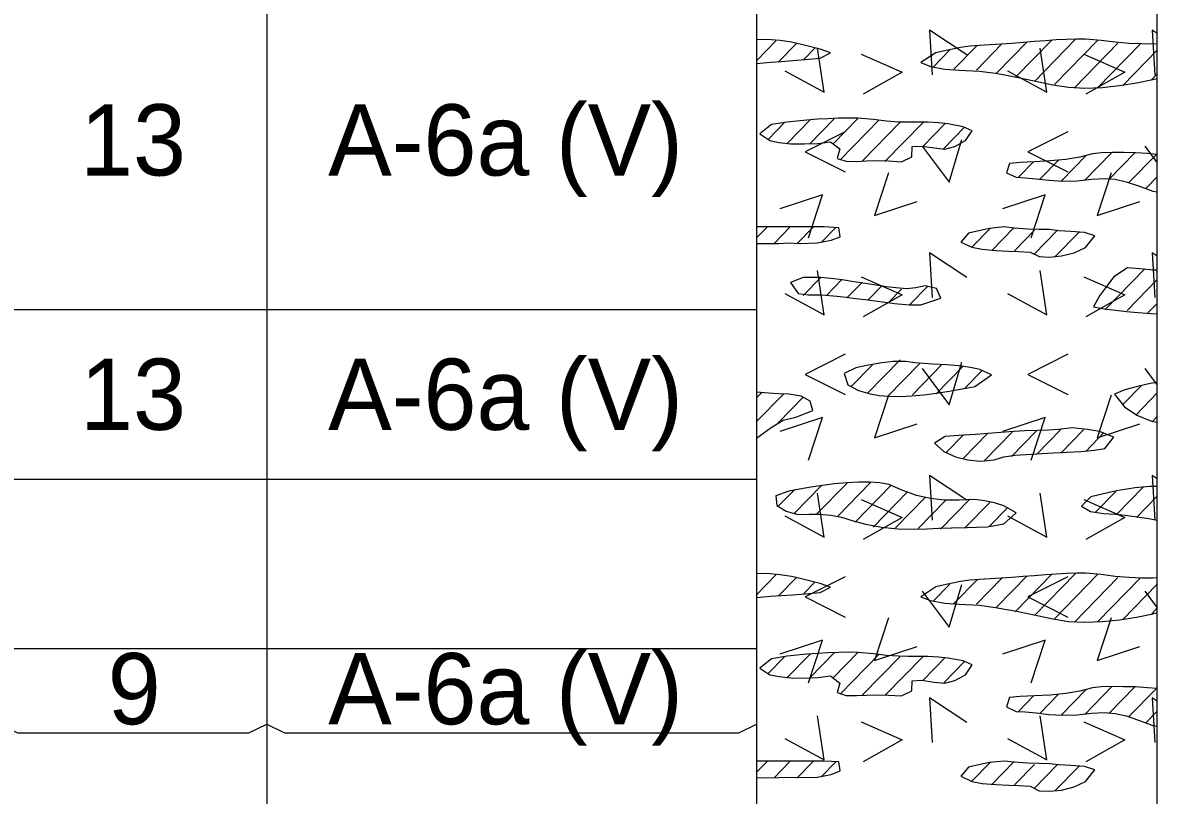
# Model space of a CAD drawing. Extents: x 0 to 0.833, y -0.323 to 0.608.
# Drawn here: x 0.7272 to 0.8333, y 0.2085 to 0.2808 of the extents above; entities that cross this region are included whole.
import ezdxf

# ---------------------------------------------------------------- set-up
doc = ezdxf.new("R2010")
doc.units = 0

msp = doc.modelspace()

# ---------------------------------------------------------------- linework, layer by layer
for points in [[(0, -0.32328), (0.83333, -0.32328), (0.83333, 0.60833), (0, 0.60833)], [(0.79583, 0.27704), (0.79715, 0.27715), (0.79814, 0.27722), (0.79922, 0.2773), (0.80039, 0.27739), (0.80179, 0.27751), (0.80275, 0.27802), (0.80179, 0.27836), (0.80091, 0.27858), (0.80003, 0.2788), (0.79909, 0.27901), (0.79803, 0.27917), (0.79677, 0.27927), (0.79583, 0.27925)], [(0.82816, 0.27479), (0.82978, 0.27496), (0.83137, 0.27521), (0.8329, 0.27552), (0.83333, 0.27563), (0.83333, 0.27887), (0.83295, 0.27884), (0.83188, 0.27886), (0.83071, 0.27891), (0.82938, 0.27901), (0.82807, 0.27918), (0.82662, 0.2793), (0.82576, 0.2793), (0.82484, 0.27928), (0.82387, 0.27923), (0.82286, 0.27916), (0.82182, 0.27908), (0.82077, 0.27899), (0.81973, 0.27891), (0.81872, 0.27884), (0.81715, 0.27874), (0.81579, 0.27865), (0.81491, 0.27852), (0.81357, 0.27824), (0.8126, 0.27803), (0.81121, 0.27711), (0.8121, 0.27675), (0.81345, 0.2765), (0.81479, 0.27641), (0.81668, 0.27631), (0.81818, 0.27611), (0.81905, 0.27596), (0.82, 0.27578), (0.82107, 0.27557), (0.82225, 0.27532), (0.82357, 0.27503), (0.82501, 0.2748), (0.82656, 0.27473)], [(0.79708, 0.26981), (0.79794, 0.26963), (0.79904, 0.26952), (0.80028, 0.26949), (0.80156, 0.26954), (0.80274, 0.2697), (0.80361, 0.26903), (0.80338, 0.26814), (0.80422, 0.26787), (0.80517, 0.26785), (0.80613, 0.2679), (0.8072, 0.26793), (0.80818, 0.2679), (0.80939, 0.26783), (0.81037, 0.2683), (0.81038, 0.26924), (0.8113, 0.2693), (0.81244, 0.26912), (0.81346, 0.26901), (0.81438, 0.26927), (0.81539, 0.26981), (0.81601, 0.27072), (0.81517, 0.2711), (0.81374, 0.27137), (0.81285, 0.27146), (0.81187, 0.27152), (0.81, 0.27152), (0.8091, 0.27154), (0.808, 0.27162), (0.80678, 0.27177), (0.8053, 0.2719), (0.80443, 0.27192), (0.80349, 0.2719), (0.80251, 0.27186), (0.80152, 0.2718), (0.80054, 0.27172), (0.79959, 0.27163), (0.7987, 0.27153), (0.79722, 0.27131), (0.79614, 0.27043)], [(0.83241, 0.26859), (0.83129, 0.26866), (0.83017, 0.26869), (0.8291, 0.2687), (0.82811, 0.26866), (0.82728, 0.26857), (0.82608, 0.26827), (0.82476, 0.26804), (0.8233, 0.26791), (0.82183, 0.26782), (0.82051, 0.26776), (0.81951, 0.26767), (0.81922, 0.2668), (0.82013, 0.26638), (0.82097, 0.26633), (0.822, 0.26623), (0.82318, 0.2661), (0.82448, 0.26601), (0.82584, 0.26604), (0.82719, 0.2662), (0.82836, 0.26627), (0.8294, 0.26619), (0.83043, 0.26595), (0.83156, 0.26556), (0.83291, 0.26507), (0.83333, 0.265), (0.83333, 0.26852)], [(0.79583, 0.26018), (0.79676, 0.26017), (0.79792, 0.26019), (0.79882, 0.26023), (0.79992, 0.26018), (0.80151, 0.26023), (0.80282, 0.26048), (0.80367, 0.2608), (0.80354, 0.26164), (0.80216, 0.26173), (0.79583, 0.26173)], [(0.81822, 0.25953), (0.81944, 0.25947), (0.82033, 0.25943), (0.82145, 0.25937), (0.82229, 0.25895), (0.82324, 0.25891), (0.82438, 0.25901), (0.82555, 0.2593), (0.82662, 0.25981), (0.82749, 0.2609), (0.82651, 0.26121), (0.82524, 0.26131), (0.82413, 0.26137), (0.82324, 0.26148), (0.82226, 0.2615), (0.82121, 0.26152), (0.81995, 0.26161), (0.81902, 0.26173), (0.81761, 0.26159), (0.81566, 0.26114), (0.81496, 0.26031), (0.81598, 0.25982), (0.81695, 0.25964)], [(0.80066, 0.25538), (0.80188, 0.25537), (0.80339, 0.25524), (0.80423, 0.25515), (0.8051, 0.25504), (0.806, 0.25492), (0.80692, 0.2548), (0.80784, 0.25468), (0.80875, 0.25457), (0.81014, 0.25443), (0.81119, 0.25444), (0.81222, 0.25478), (0.81308, 0.25507), (0.81267, 0.25597), (0.8116, 0.25622), (0.81075, 0.25602), (0.80989, 0.25594), (0.80885, 0.25602), (0.80799, 0.25613), (0.80703, 0.25627), (0.806, 0.25644), (0.80492, 0.2566), (0.80384, 0.25676), (0.8028, 0.25689), (0.80182, 0.25698), (0.8002, 0.25699), (0.79901, 0.25652), (0.79974, 0.25548)], [(0.83305, 0.25768), (0.83171, 0.25779), (0.83054, 0.25789), (0.82925, 0.25707), (0.82857, 0.25616), (0.82792, 0.25527), (0.82735, 0.25425), (0.82858, 0.25402), (0.82945, 0.25392), (0.83045, 0.25382), (0.83155, 0.25373), (0.83272, 0.25363), (0.83333, 0.25358), (0.83333, 0.25767)], [(0.81233, 0.24887), (0.81063, 0.24899), (0.80977, 0.24912), (0.8086, 0.24913), (0.80755, 0.24899), (0.80632, 0.24879), (0.80513, 0.24854), (0.80403, 0.24802), (0.80436, 0.24696), (0.80536, 0.2464), (0.80647, 0.2461), (0.8073, 0.24595), (0.80824, 0.24587), (0.80926, 0.24586), (0.81035, 0.24591), (0.81149, 0.24601), (0.81267, 0.24616), (0.81386, 0.24635), (0.81506, 0.24656), (0.81625, 0.24679), (0.81783, 0.24787), (0.81673, 0.24837), (0.81585, 0.24857), (0.8148, 0.24873), (0.81361, 0.24883)], [(0.83265, 0.24706), (0.83136, 0.24675), (0.83028, 0.24647), (0.82934, 0.24608), (0.83026, 0.24488), (0.83142, 0.24412), (0.83279, 0.24354), (0.83333, 0.24344), (0.83333, 0.24715)], [(0.79583, 0.24196), (0.79719, 0.24295), (0.79831, 0.24365), (0.79951, 0.24393), (0.80111, 0.24453), (0.80086, 0.24541), (0.80002, 0.24589), (0.79889, 0.24608), (0.79791, 0.24611), (0.79694, 0.24617), (0.79583, 0.24625)], [(0.82537, 0.24291), (0.82408, 0.24276), (0.82319, 0.2427), (0.82214, 0.24267), (0.82091, 0.24264), (0.81947, 0.24255), (0.81792, 0.24242), (0.81632, 0.2423), (0.81475, 0.24221), (0.81348, 0.24211), (0.81247, 0.24147), (0.81337, 0.24071), (0.81444, 0.24021), (0.81561, 0.23992), (0.81675, 0.23981), (0.81807, 0.23993), (0.81896, 0.2402), (0.82003, 0.24035), (0.82157, 0.24047), (0.82253, 0.24053), (0.82362, 0.24058), (0.82483, 0.24065), (0.82618, 0.24071), (0.82745, 0.24082), (0.82842, 0.24099), (0.82927, 0.24205), (0.82791, 0.24257), (0.82679, 0.24277)], [(0.79885, 0.237), (0.79763, 0.23654), (0.79773, 0.23564), (0.79859, 0.23512), (0.7997, 0.23482), (0.80074, 0.23483), (0.80165, 0.23484), (0.80281, 0.23476), (0.80377, 0.23455), (0.80486, 0.2342), (0.80606, 0.23391), (0.80751, 0.23363), (0.80905, 0.23345), (0.81052, 0.23342), (0.81177, 0.23347), (0.81289, 0.23352), (0.81408, 0.23355), (0.81553, 0.23359), (0.81642, 0.23362), (0.81745, 0.23365), (0.81897, 0.23392), (0.82011, 0.23496), (0.81896, 0.23563), (0.8181, 0.23589), (0.81717, 0.23609), (0.81626, 0.2362), (0.81479, 0.23614), (0.81343, 0.23614), (0.8121, 0.23629), (0.8108, 0.23659), (0.80953, 0.23705), (0.8082, 0.2376), (0.80736, 0.23776), (0.8064, 0.23784), (0.80536, 0.23784), (0.80427, 0.23778), (0.80314, 0.23767), (0.80201, 0.23752), (0.8009, 0.23735), (0.79984, 0.23717)], [(0.83263, 0.23744), (0.83126, 0.23731), (0.82969, 0.23704), (0.82883, 0.23687), (0.82712, 0.23646), (0.82623, 0.23559), (0.82708, 0.2351), (0.82831, 0.23491), (0.82941, 0.23484), (0.83033, 0.23475), (0.83165, 0.23457), (0.83253, 0.23443), (0.83333, 0.23429), (0.83333, 0.23744)], [(0.79583, 0.22704), (0.79715, 0.22715), (0.79814, 0.22722), (0.79922, 0.2273), (0.80039, 0.22739), (0.80179, 0.22751), (0.80275, 0.22802), (0.80179, 0.22836), (0.80091, 0.22858), (0.80003, 0.2288), (0.79909, 0.22901), (0.79803, 0.22917), (0.79677, 0.22927), (0.79583, 0.22925)], [(0.82816, 0.22479), (0.82978, 0.22496), (0.83137, 0.22521), (0.8329, 0.22552), (0.83333, 0.22563), (0.83333, 0.22887), (0.83295, 0.22884), (0.83188, 0.22886), (0.83071, 0.22891), (0.82938, 0.22901), (0.82807, 0.22918), (0.82662, 0.2293), (0.82576, 0.2293), (0.82484, 0.22928), (0.82387, 0.22923), (0.82286, 0.22916), (0.82182, 0.22908), (0.82077, 0.22899), (0.81973, 0.22891), (0.81872, 0.22884), (0.81715, 0.22874), (0.81579, 0.22865), (0.81491, 0.22852), (0.81357, 0.22824), (0.8126, 0.22803), (0.81121, 0.22711), (0.8121, 0.22675), (0.81345, 0.2265), (0.81479, 0.22641), (0.81668, 0.22631), (0.81818, 0.22611), (0.81905, 0.22596), (0.82, 0.22578), (0.82107, 0.22557), (0.82225, 0.22532), (0.82357, 0.22503), (0.82501, 0.2248), (0.82656, 0.22473)], [(0.79708, 0.21981), (0.79794, 0.21963), (0.79904, 0.21952), (0.80028, 0.21949), (0.80156, 0.21954), (0.80274, 0.2197), (0.80361, 0.21903), (0.80338, 0.21814), (0.80422, 0.21787), (0.80517, 0.21785), (0.80613, 0.2179), (0.8072, 0.21793), (0.80818, 0.2179), (0.80939, 0.21783), (0.81037, 0.2183), (0.81038, 0.21924), (0.8113, 0.2193), (0.81244, 0.21912), (0.81346, 0.21901), (0.81438, 0.21927), (0.81539, 0.21981), (0.81601, 0.22072), (0.81517, 0.2211), (0.81374, 0.22137), (0.81285, 0.22146), (0.81187, 0.22152), (0.81, 0.22152), (0.8091, 0.22154), (0.808, 0.22162), (0.80678, 0.22177), (0.8053, 0.2219), (0.80443, 0.22192), (0.80349, 0.2219), (0.80251, 0.22186), (0.80152, 0.2218), (0.80054, 0.22172), (0.79959, 0.22163), (0.7987, 0.22153), (0.79722, 0.22131), (0.79614, 0.22043)], [(0.83241, 0.21859), (0.83129, 0.21866), (0.83017, 0.21869), (0.8291, 0.2187), (0.82811, 0.21866), (0.82728, 0.21857), (0.82608, 0.21827), (0.82476, 0.21804), (0.8233, 0.21791), (0.82183, 0.21782), (0.82051, 0.21776), (0.81951, 0.21767), (0.81922, 0.2168), (0.82013, 0.21638), (0.82097, 0.21633), (0.822, 0.21623), (0.82318, 0.2161), (0.82448, 0.21601), (0.82584, 0.21604), (0.82719, 0.2162), (0.82836, 0.21627), (0.8294, 0.21619), (0.83043, 0.21595), (0.83156, 0.21556), (0.83291, 0.21507), (0.83333, 0.215), (0.83333, 0.21852)], [(0.79583, 0.21018), (0.79676, 0.21017), (0.79792, 0.21019), (0.79882, 0.21023), (0.79992, 0.21018), (0.80151, 0.21023), (0.80282, 0.21048), (0.80367, 0.2108), (0.80354, 0.21164), (0.80216, 0.21173), (0.79583, 0.21173)], [(0.81822, 0.20953), (0.81944, 0.20948), (0.82033, 0.20943), (0.82145, 0.20937), (0.82229, 0.20895), (0.82324, 0.20891), (0.82438, 0.20901), (0.82555, 0.2093), (0.82662, 0.20981), (0.82749, 0.2109), (0.82651, 0.21121), (0.82524, 0.21131), (0.82413, 0.21137), (0.82324, 0.21148), (0.82226, 0.2115), (0.82121, 0.21152), (0.81995, 0.21161), (0.81902, 0.21173), (0.81761, 0.21159), (0.81566, 0.21114), (0.81496, 0.21031), (0.81598, 0.20982), (0.81695, 0.20964)]]:
    msp.add_lwpolyline(points, close=True)
for points in [[(0.75, 0.55417), (0.75, -0.28575)], [(0.75, 0.55417), (0.75, -0.28575)], [(0.79583, 0.55417), (0.79583, -0.28575)], [(0.83333, -0.28575), (0.83333, 0.50165)], [(0.81551, 0.27783), (0.81201, 0.28014), (0.81226, 0.27595)], [(0.82569, 0.27929), (0.82184, 0.27535)], [(0.83333, 0.27982), (0.83284, 0.28014), (0.83309, 0.27595)], [(0.79765, 0.27915), (0.79583, 0.27728)], [(0.7996, 0.27894), (0.79786, 0.27715)], [(0.79847, 0.27634), (0.80215, 0.27434), (0.80153, 0.27847)], [(0.8013, 0.27846), (0.80027, 0.27741)], [(0.81392, 0.2783), (0.81235, 0.27669)], [(0.8143, 0.27648), (0.8165, 0.27873)], [(0.8164, 0.27641), (0.81879, 0.27886)], [(0.81829, 0.27613), (0.82114, 0.27905)], [(0.8193, 0.27634), (0.82299, 0.27434), (0.82236, 0.27847)], [(0.82004, 0.27571), (0.82346, 0.27922)], [(0.82775, 0.27919), (0.8237, 0.27505)], [(0.82964, 0.27892), (0.82557, 0.27474)], [(0.83173, 0.27885), (0.82774, 0.27476)], [(0.83333, 0.27827), (0.83012, 0.27498)], [(0.80562, 0.27789), (0.80946, 0.27621), (0.80581, 0.27414)], [(0.82645, 0.27789), (0.83029, 0.27621), (0.82664, 0.27414)], [(0.83281, 0.27552), (0.83333, 0.27606)], [(0.80083, 0.26951), (0.80311, 0.27185)], [(0.80534, 0.27192), (0.80299, 0.26951)], [(0.79844, 0.27149), (0.79691, 0.26992)], [(0.79871, 0.26955), (0.80085, 0.27174)], [(0.80367, 0.268), (0.80732, 0.27174)], [(0.80571, 0.26788), (0.80924, 0.27149)], [(0.81142, 0.27151), (0.80785, 0.26786)], [(0.81141, 0.26929), (0.81348, 0.27141)], [(0.81528, 0.27105), (0.81331, 0.26903)], [(0.80412, 0.27063), (0.80038, 0.26876), (0.80412, 0.26688)], [(0.81134, 0.26929), (0.81384, 0.26591), (0.81503, 0.26991)], [(0.82496, 0.27063), (0.82121, 0.26876), (0.82496, 0.26688)], [(0.82909, 0.2687), (0.82656, 0.2661)], [(0.82885, 0.26623), (0.83122, 0.26866)], [(0.83217, 0.26929), (0.83333, 0.26773)], [(0.82035, 0.26637), (0.82176, 0.26782)], [(0.82233, 0.26619), (0.82408, 0.26798)], [(0.82433, 0.26602), (0.82666, 0.26841)], [(0.83325, 0.26852), (0.83065, 0.26586)], [(0.80818, 0.2668), (0.80687, 0.2628), (0.81087, 0.26411)], [(0.82901, 0.2668), (0.8277, 0.2628), (0.8317, 0.26411)], [(0.83333, 0.2664), (0.83227, 0.26531)], [(0.80069, 0.26072), (0.802, 0.26472), (0.798, 0.26341)], [(0.82152, 0.26072), (0.82284, 0.26472), (0.81884, 0.26341)], [(0.79583, 0.2607), (0.79681, 0.2617)], [(0.79898, 0.26172), (0.79747, 0.26017)], [(0.80116, 0.26173), (0.79959, 0.26013)], [(0.80328, 0.26169), (0.80188, 0.26026)], [(0.8177, 0.26159), (0.81596, 0.25981)], [(0.81988, 0.26161), (0.81785, 0.25953)], [(0.82185, 0.26142), (0.81997, 0.25949)], [(0.824, 0.26141), (0.82178, 0.25913)], [(0.82601, 0.26125), (0.82378, 0.25897)], [(0.81551, 0.25699), (0.81201, 0.25931), (0.81226, 0.25512)], [(0.83333, 0.25898), (0.83284, 0.25931), (0.83309, 0.25512)], [(0.79847, 0.25551), (0.80215, 0.25351), (0.80153, 0.25764)], [(0.80188, 0.25703), (0.8002, 0.25531)], [(0.80562, 0.25706), (0.80946, 0.25537), (0.80581, 0.25331)], [(0.8193, 0.25551), (0.82299, 0.25351), (0.82236, 0.25764)], [(0.82645, 0.25706), (0.83029, 0.25537), (0.82664, 0.25331)], [(0.83217, 0.25781), (0.82844, 0.25399)], [(0.8038, 0.25679), (0.80237, 0.25532)], [(0.80575, 0.25657), (0.80429, 0.25508)], [(0.80758, 0.25624), (0.80627, 0.25489)], [(0.80941, 0.2559), (0.80816, 0.25462)], [(0.81188, 0.25621), (0.81016, 0.25446)], [(0.83333, 0.25679), (0.83052, 0.25391)], [(0.725, 0.254), (0.75, 0.254)], [(0.75, 0.254), (0.79583, 0.254)], [(0.83333, 0.25457), (0.83245, 0.25367)], [(0.80412, 0.2498), (0.80038, 0.24792), (0.80412, 0.24605)], [(0.82496, 0.2498), (0.82121, 0.24792), (0.82496, 0.24605)], [(0.80465, 0.24675), (0.80667, 0.24883)], [(0.80626, 0.24619), (0.80928, 0.24928)], [(0.80809, 0.24585), (0.81111, 0.24895)], [(0.81041, 0.24602), (0.81318, 0.24885)], [(0.81134, 0.24846), (0.81384, 0.24508), (0.81503, 0.24908)], [(0.81264, 0.24609), (0.81518, 0.24869)], [(0.83217, 0.24846), (0.83333, 0.2469)], [(0.81536, 0.24667), (0.81699, 0.24833)], [(0.8301, 0.24509), (0.83184, 0.24688)], [(0.7963, 0.24621), (0.79583, 0.24572)], [(0.79834, 0.24608), (0.79583, 0.24351)], [(0.79786, 0.24338), (0.80023, 0.24581)], [(0.80818, 0.24597), (0.80687, 0.24197), (0.81087, 0.24328)], [(0.82901, 0.24597), (0.8277, 0.24197), (0.8317, 0.24328)], [(0.83131, 0.24412), (0.83333, 0.24619)], [(0.80069, 0.23989), (0.802, 0.24389), (0.798, 0.24257)], [(0.82152, 0.23989), (0.82284, 0.24389), (0.81884, 0.24257)], [(0.83285, 0.24349), (0.83333, 0.24398)], [(0.81519, 0.24228), (0.81354, 0.24058)], [(0.81514, 0.24001), (0.81748, 0.24241)], [(0.81709, 0.2398), (0.81974, 0.24251)], [(0.8197, 0.24025), (0.82203, 0.24265)], [(0.82202, 0.24042), (0.8243, 0.24275)], [(0.82431, 0.24055), (0.82644, 0.24274)], [(0.82663, 0.24071), (0.82834, 0.24247)], [(0.725, 0.23812), (0.75, 0.23812)], [(0.75, 0.23812), (0.79583, 0.23812)], [(0.80653, 0.23783), (0.8034, 0.23461)], [(0.81551, 0.23616), (0.81201, 0.23847), (0.81226, 0.23428)], [(0.83333, 0.23815), (0.83284, 0.23847), (0.83309, 0.23428)], [(0.79938, 0.23713), (0.79786, 0.23558)], [(0.79847, 0.23468), (0.80215, 0.23268), (0.80153, 0.2368)], [(0.79933, 0.23487), (0.80195, 0.23756)], [(0.80142, 0.2348), (0.8043, 0.23775)], [(0.80506, 0.2341), (0.8084, 0.23753)], [(0.80997, 0.23693), (0.80675, 0.23362)], [(0.8193, 0.23468), (0.82299, 0.23268), (0.82236, 0.2368)], [(0.82751, 0.23498), (0.82945, 0.23696)], [(0.83203, 0.23739), (0.82949, 0.23479)], [(0.80562, 0.23622), (0.80946, 0.23454), (0.80581, 0.23248)], [(0.81164, 0.23642), (0.80884, 0.23356)], [(0.81353, 0.23614), (0.81094, 0.23349)], [(0.81303, 0.23342), (0.81579, 0.23625)], [(0.81534, 0.23358), (0.81768, 0.23597)], [(0.82645, 0.23622), (0.83029, 0.23454), (0.82664, 0.23248)], [(0.83138, 0.23452), (0.83333, 0.23652)], [(0.8176, 0.23368), (0.81934, 0.23547)], [(0.83333, 0.2343), (0.83333, 0.23431)], [(0.79765, 0.22915), (0.79583, 0.22728)], [(0.7996, 0.22894), (0.79786, 0.22715)], [(0.8013, 0.22846), (0.80027, 0.22741)], [(0.80412, 0.22896), (0.80038, 0.22709), (0.80412, 0.22521)], [(0.81392, 0.2283), (0.81235, 0.22669)], [(0.8143, 0.22648), (0.8165, 0.22873)], [(0.8164, 0.22641), (0.81879, 0.22886)], [(0.81829, 0.22613), (0.82114, 0.22905)], [(0.82004, 0.22571), (0.82346, 0.22922)], [(0.82496, 0.22896), (0.82121, 0.22709), (0.82496, 0.22521)], [(0.82569, 0.22929), (0.82184, 0.22535)], [(0.82775, 0.22919), (0.8237, 0.22505)], [(0.82964, 0.22892), (0.82557, 0.22474)], [(0.83173, 0.22885), (0.82774, 0.22476)], [(0.83333, 0.22827), (0.83012, 0.22498)], [(0.81134, 0.22762), (0.81384, 0.22425), (0.81503, 0.22825)], [(0.83217, 0.22762), (0.83333, 0.22606)], [(0.80818, 0.22513), (0.80687, 0.22113), (0.81087, 0.22245)], [(0.82901, 0.22513), (0.8277, 0.22113), (0.8317, 0.22245)], [(0.83281, 0.22552), (0.83333, 0.22606)], [(0.80069, 0.21905), (0.802, 0.22305), (0.798, 0.22174)], [(0.82152, 0.21905), (0.82284, 0.22305), (0.81884, 0.22174)], [(0.725, 0.22225), (0.75, 0.22225)], [(0.75, 0.22225), (0.79583, 0.22225)], [(0.80534, 0.22192), (0.80299, 0.21951)], [(0.79844, 0.22149), (0.79691, 0.21992)], [(0.79871, 0.21955), (0.80085, 0.22174)], [(0.80083, 0.21951), (0.80311, 0.22185)], [(0.80367, 0.218), (0.80732, 0.22174)], [(0.80571, 0.21788), (0.80924, 0.22149)], [(0.81142, 0.22151), (0.80785, 0.21786)], [(0.81141, 0.21929), (0.81348, 0.22141)], [(0.81528, 0.22105), (0.81331, 0.21903)], [(0.82035, 0.21637), (0.82176, 0.21782)], [(0.82233, 0.21619), (0.82408, 0.21798)], [(0.82433, 0.21602), (0.82666, 0.21841)], [(0.82909, 0.2187), (0.82656, 0.2161)], [(0.82885, 0.21623), (0.83122, 0.21866)], [(0.83325, 0.21852), (0.83065, 0.21586)], [(0.81551, 0.21533), (0.81201, 0.21764), (0.81226, 0.21345)], [(0.83333, 0.21732), (0.83284, 0.21764), (0.83309, 0.21345)], [(0.79847, 0.21384), (0.80215, 0.21184), (0.80153, 0.21597)], [(0.8193, 0.21384), (0.82299, 0.21184), (0.82236, 0.21597)], [(0.83333, 0.2164), (0.83227, 0.21531)], [(0.725, 0.21519), (0.72667, 0.21437), (0.74833, 0.21437), (0.75, 0.21519)], [(0.75, 0.21519), (0.75167, 0.21437), (0.79417, 0.21437), (0.79583, 0.21519)], [(0.80562, 0.21539), (0.80946, 0.21371), (0.80581, 0.21164)], [(0.82645, 0.21539), (0.83029, 0.21371), (0.82664, 0.21164)], [(0.79583, 0.2107), (0.79681, 0.2117)], [(0.79898, 0.21172), (0.79747, 0.21017)], [(0.80116, 0.21173), (0.79959, 0.21013)], [(0.80328, 0.21169), (0.80188, 0.21026)], [(0.8177, 0.21159), (0.81596, 0.20981)], [(0.81988, 0.21161), (0.81785, 0.20953)], [(0.82185, 0.21142), (0.81997, 0.20949)], [(0.824, 0.21141), (0.82178, 0.20913)], [(0.82601, 0.21125), (0.82378, 0.20897)]]:
    msp.add_lwpolyline(points)

# ---------------------------------------------------------------- texts
for s, height, p in [('13', 0.006667, (0.73253, 0.26654)), ('A-6a (V)', 0.006667, (0.75575, 0.26654)), ('13', 0.006667, (0.73253, 0.24273)), ('A-6a (V)', 0.006667, (0.75575, 0.24273)), ('9', 0.00667, (0.73512, 0.21517)), ('A-6a (V)', 0.006667, (0.75575, 0.21517))]:
    msp.add_text(s, height=height).set_placement(p)

doc.saveas('drawing.dxf')
